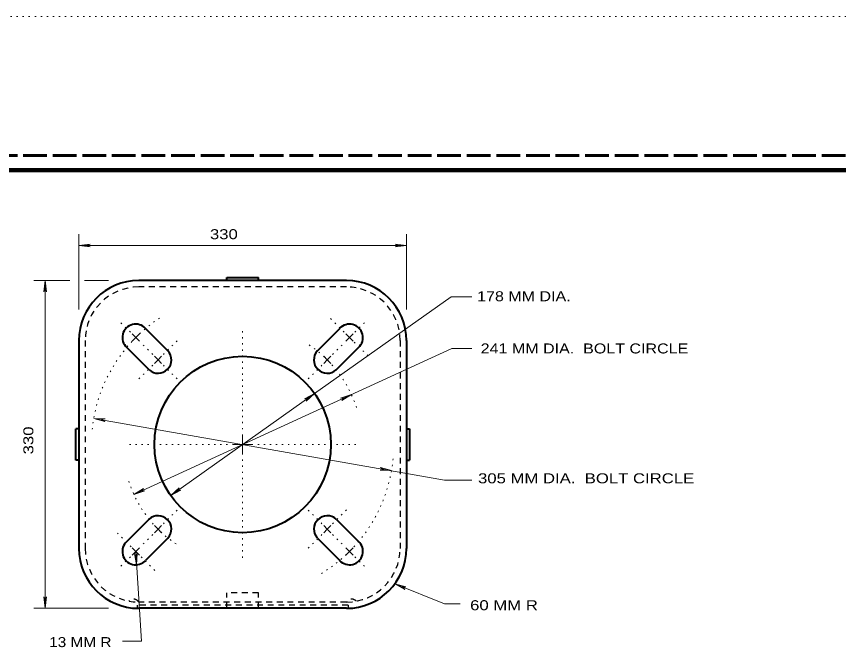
# Model space of a CAD drawing. Extents: x 312583 to 312854, y 144419 to 144597.
# Drawn here: x 312655.9 to 312718.5, y 144548.2 to 144596.8 of the extents above; entities that cross this region are included whole.
import ezdxf

# ---------------------------------------------------------------- set-up
doc = ezdxf.new("R2010")
doc.units = 0
doc.header["$LTSCALE"] = 0.3
for name, pattern in [('DOTTED', [1.5, 0.3, -1.2]), ('LONG_DASHED', [7.5, 6, -1.5]), ('SHORT_DASHED', [2.7, 1.5, -1.2])]:
    doc.linetypes.add(name, pattern=pattern)
for name, color, linetype, lineweight in [('1', 7, 'Continuous', 40), ('2', 7, 'Continuous', 13), ('63', 7, 'DOTTED', 13)]:
    doc.layers.add(name, color=color, linetype=linetype, lineweight=lineweight)

msp = doc.modelspace()

# ---------------------------------------------------------------- linework, layer by layer
at = {"layer": '1', "linetype": 'LONG_DASHED', "lineweight": 60}
msp.add_line((312851.75, 144586.2246), (312583.526, 144586.2246), dxfattribs=at)
at = {"layer": '1'}
for p, q in [((312681.0453, 144576.7003), (312665.2366, 144576.7003)), ((312671.945, 144576.938), (312674.337, 144576.938)), ((312667.46, 144571.3566), (312665.758, 144573.0586)), ((312678.822, 144571.3566), (312680.524, 144573.0586)), ((312660.6826, 144572.1463), (312660.6826, 144556.33)), ((312685.5993, 144572.1463), (312685.5993, 144556.33)), ((312666.0263, 144569.9153), (312664.3243, 144571.6173)), ((312680.2556, 144569.9153), (312681.9576, 144571.6173)), ((312660.445, 144563.0383), (312660.445, 144565.438)), ((312685.837, 144565.438), (312685.837, 144563.0383)), ((312666.0263, 144558.561), (312664.3243, 144556.859)), ((312680.2556, 144558.561), (312681.9576, 144556.859)), ((312667.46, 144557.1196), (312665.758, 144555.4176)), ((312678.822, 144557.1196), (312680.524, 144555.4176)), ((312681.0453, 144551.7836), (312665.2366, 144551.7836))]:
    msp.add_line(p, q, dxfattribs=at)
at = {"layer": '1', "linetype": 'SHORT_DASHED', "lineweight": 25}
for p, q in [((312681.0453, 144576.2173), (312665.2366, 144576.2173)), ((312661.158, 144572.1463), (312661.158, 144556.33)), ((312685.1163, 144572.1463), (312685.1163, 144556.33)), ((312674.337, 144552.972), (312671.945, 144552.972)), ((312681.0453, 144552.259), (312665.2366, 144552.259)), ((312665.114, 144552.0213), (312665.114, 144551.7836)), ((312681.168, 144552.0213), (312665.114, 144552.0213)), ((312681.168, 144552.0213), (312681.168, 144551.7836))]:
    msp.add_line(p, q, dxfattribs=at)
at = {"layer": '1', "lineweight": 158}
msp.add_lwpolyline([(312616.5, 144423.1446), (312616.5, 144585.0846), (312849, 144585.0846)], dxfattribs=at)
at = {"layer": '1'}
msp.add_circle((312673.139, 144564.2401), 6.7083, dxfattribs=at)
for centre, radius, start, end in [((312665.2328, 144572.1463), 4.5521, 90, 180), ((312681.0453, 144572.1463), 4.5521, 0, 90), ((312665.0066, 144572.3725), 1.0182, 42.40437, 227.592), ((312681.2715, 144572.3725), 1.0182, 312.40437, 137.592), ((312666.701, 144570.6781), 1.0182, 228.20522, 41.75743), ((312679.5771, 144570.6781), 1.0182, 138.20522, 311.75743), ((312666.701, 144557.802), 1.0182, 318.20522, 131.75743), ((312679.5771, 144557.802), 1.0182, 48.20522, 221.75743), ((312665.0066, 144556.1076), 1.0182, 132.40437, 317.592), ((312681.2715, 144556.1076), 1.0182, 222.40437, 47.592), ((312665.2328, 144556.3338), 4.5521, 180, 270), ((312681.0453, 144556.3338), 4.5521, 270, 0)]:
    msp.add_arc(centre, radius, start, end, dxfattribs=at)
at = {"layer": '1', "linetype": 'SHORT_DASHED', "lineweight": 25}
for centre, radius, start, end in [((312665.2328, 144572.1463), 4.0729, 90, 180), ((312681.0453, 144572.1463), 4.0729, 0, 90), ((312665.2328, 144556.3338), 4.0729, 180, 270), ((312681.0453, 144556.3338), 4.0729, 270, 0), ((312664.8359, 144552.0127), 0.4681, 32.01849, 137.4851), ((312681.4422, 144552.0127), 0.4681, 42.5149, 147.98151)]:
    msp.add_arc(centre, radius, start, end, dxfattribs=at)
at = {"layer": '1', "linetype": 'DOTTED', "lineweight": 13}
for start, end in [(17.97781, 57.71845), (197.8997, 238.39092)]:
    msp.add_arc((312673.139, 144564.2401), 9.1048, start, end, dxfattribs=at)
at = {"layer": '2'}
for p, q in [((312660.6826, 144574.4923), (312660.6826, 144580.2423)), ((312685.5993, 144574.4923), (312685.5993, 144580.2423)), ((312660.6826, 144579.3683), (312661.549, 144579.4756)), ((312685.5993, 144579.3683), (312660.6826, 144579.3683)), ((312660.6826, 144579.3683), (312661.549, 144579.261)), ((312661.549, 144579.4756), (312661.273, 144579.3683)), ((312661.549, 144579.261), (312661.273, 144579.3683)), ((312684.733, 144579.4756), (312685.009, 144579.3683)), ((312685.5993, 144579.3683), (312684.733, 144579.4756)), ((312684.733, 144579.261), (312685.009, 144579.3683)), ((312685.5993, 144579.3683), (312684.733, 144579.261)), ((312659.9926, 144576.7003), (312657.248, 144576.7003)), ((312658.122, 144576.7003), (312658.0146, 144575.834)), ((312658.122, 144551.7836), (312658.122, 144576.7003)), ((312658.122, 144576.7003), (312658.2293, 144575.834)), ((312662.9366, 144576.7003), (312661.1196, 144576.7003)), ((312658.0146, 144575.834), (312658.122, 144576.11)), ((312658.2293, 144575.834), (312658.122, 144576.11)), ((312665.0066, 144572.3686), (312664.7383, 144572.6446)), ((312665.0066, 144572.3686), (312664.7383, 144572.1003)), ((312665.0066, 144572.3686), (312665.2826, 144572.6446)), ((312665.0066, 144572.3686), (312665.2826, 144572.1003)), ((312681.2753, 144572.3686), (312680.9993, 144572.6446)), ((312681.2753, 144572.3686), (312680.9993, 144572.1003)), ((312681.2753, 144572.3686), (312681.5436, 144572.6446)), ((312681.2753, 144572.3686), (312681.5436, 144572.1003)), ((312664.861, 144560.447), (312689.0646, 144571.5406)), ((312689.0646, 144571.5406), (312690.5826, 144571.5406)), ((312666.701, 144570.6743), (312666.4326, 144570.9503)), ((312666.701, 144570.6743), (312666.977, 144570.9503)), ((312679.581, 144570.6743), (312679.305, 144570.9503)), ((312679.581, 144570.6743), (312679.8493, 144570.9503)), ((312666.701, 144570.6743), (312666.4326, 144570.406)), ((312666.701, 144570.6743), (312666.977, 144570.406)), ((312679.581, 144570.6743), (312679.305, 144570.406)), ((312679.581, 144570.6743), (312679.8493, 144570.406)), ((312667.667, 144560.3626), (312678.615, 144568.1136)), ((312678.615, 144568.1213), (312677.8483, 144567.7073)), ((312677.8483, 144567.7073), (312678.132, 144567.7763)), ((312678.615, 144568.1213), (312677.971, 144567.531)), ((312677.971, 144567.531), (312678.132, 144567.7763)), ((312681.4133, 144568.037), (312680.5853, 144567.7686)), ((312680.5853, 144567.7686), (312680.8766, 144567.7916)), ((312681.4133, 144568.037), (312680.6773, 144567.577)), ((312680.6773, 144567.577), (312680.8766, 144567.7916)), ((312661.8096, 144566.2276), (312688.505, 144561.5356)), ((312661.8096, 144566.2276), (312662.6453, 144565.9746)), ((312661.8096, 144566.2276), (312662.6836, 144566.1893)), ((312662.6836, 144566.1893), (312662.3923, 144566.128)), ((312662.6453, 144565.9746), (312662.3923, 144566.128)), ((312673.141, 144564.242), (312673.141, 144565.0086)), ((312673.141, 144564.242), (312672.3743, 144564.242)), ((312673.141, 144564.242), (312673.9076, 144564.242)), ((312673.141, 144564.242), (312673.141, 144563.4753)), ((312683.5983, 144562.2946), (312683.8896, 144562.3483)), ((312684.4646, 144562.2486), (312683.5983, 144562.2946)), ((312683.6366, 144562.5016), (312683.8896, 144562.3483)), ((312684.4646, 144562.2486), (312683.6366, 144562.5016)), ((312688.505, 144561.5356), (312690.5826, 144561.5356)), ((312664.861, 144560.447), (312665.6046, 144560.8993)), ((312665.6046, 144560.8993), (312665.3976, 144560.6923)), ((312667.667, 144560.3626), (312668.311, 144560.9453)), ((312668.311, 144560.9453), (312668.15, 144560.7)), ((312664.861, 144560.447), (312665.6966, 144560.7076)), ((312665.6966, 144560.7076), (312665.3976, 144560.6923)), ((312667.667, 144560.3626), (312668.4336, 144560.7766)), ((312668.4336, 144560.7766), (312668.15, 144560.7)), ((312666.701, 144557.802), (312666.4326, 144558.0703)), ((312666.701, 144557.802), (312666.4326, 144557.526)), ((312666.701, 144557.802), (312666.977, 144558.0703)), ((312666.701, 144557.802), (312666.977, 144557.526)), ((312679.581, 144557.802), (312679.305, 144558.0703)), ((312679.581, 144557.802), (312679.305, 144557.526)), ((312679.581, 144557.802), (312679.8493, 144558.0703)), ((312679.581, 144557.802), (312679.8493, 144557.526)), ((312665.0066, 144556.1076), (312664.7383, 144556.376)), ((312665.0066, 144556.1076), (312664.7383, 144555.8316)), ((312664.907, 144555.9466), (312665.0373, 144555.6783)), ((312665.0756, 144555.088), (312664.907, 144555.9466)), ((312665.0066, 144556.1076), (312665.2826, 144556.376)), ((312665.0066, 144556.1076), (312665.2826, 144555.8316)), ((312665.0066, 144556.1076), (312665.4436, 144549.292)), ((312665.1216, 144555.962), (312665.0373, 144555.6783)), ((312665.0756, 144555.088), (312665.1216, 144555.962)), ((312681.2753, 144556.1076), (312680.9993, 144556.376)), ((312681.2753, 144556.1076), (312680.9993, 144555.8316)), ((312681.2753, 144556.1076), (312681.5436, 144556.376)), ((312681.2753, 144556.1076), (312681.5436, 144555.8316)), ((312684.71, 144553.6313), (312685.4766, 144553.2096)), ((312684.71, 144553.6313), (312685.5533, 144553.409)), ((312685.4766, 144553.2096), (312685.2543, 144553.409)), ((312685.5533, 144553.409), (312685.2543, 144553.409)), ((312658.0146, 144552.65), (312658.122, 144552.374)), ((312658.122, 144551.7836), (312658.0146, 144552.65)), ((312658.2293, 144552.65), (312658.122, 144552.374)), ((312658.122, 144551.7836), (312658.2293, 144552.65)), ((312662.9366, 144551.7836), (312657.248, 144551.7836)), ((312665.4436, 144549.292), (312663.9946, 144549.292))]:
    msp.add_line(p, q, dxfattribs=at)
at = {"layer": '2', "lineweight": 40}
for p, q in [((312671.945, 144576.7003), (312671.945, 144576.938)), ((312674.337, 144576.7003), (312674.337, 144576.938)), ((312660.6826, 144565.438), (312660.445, 144565.438)), ((312685.5993, 144565.438), (312685.837, 144565.438)), ((312660.6826, 144563.0383), (312660.445, 144563.0383)), ((312685.5993, 144563.0383), (312685.837, 144563.0383))]:
    msp.add_line(p, q, dxfattribs=at)
at = {"layer": '2', "linetype": 'DOTTED'}
for p, q in [((312664.6003, 144572.775), (312663.78, 144573.5953)), ((312680.869, 144572.775), (312679.7573, 144573.8866)), ((312681.6816, 144572.775), (312682.4943, 144573.5953)), ((312673.141, 144565.392), (312673.141, 144573.0586)), ((312667.1073, 144571.0806), (312668.242, 144572.2153)), ((312666.2946, 144571.0806), (312665.39, 144571.9853)), ((312679.9873, 144571.0806), (312680.892, 144571.9853)), ((312681.628, 144572.016), (312682.8163, 144570.8353)), ((312666.2946, 144570.268), (312665.183, 144569.164)), ((312667.1073, 144570.268), (312668.15, 144569.233)), ((312679.1746, 144570.268), (312678.132, 144569.233)), ((312671.991, 144564.242), (312664.3243, 144564.242)), ((312674.291, 144564.242), (312681.9576, 144564.242)), ((312673.141, 144563.092), (312673.141, 144555.4253)), ((312667.1073, 144558.2083), (312668.15, 144559.2433)), ((312679.1746, 144558.2083), (312678.132, 144559.2433)), ((312679.9873, 144558.2083), (312681.0913, 144559.32)), ((312664.654, 144556.4603), (312663.4656, 144557.6486)), ((312666.2946, 144557.3956), (312665.39, 144556.491)), ((312679.1746, 144557.3956), (312678.04, 144556.261)), ((312679.9873, 144557.3956), (312680.892, 144556.491)), ((312664.6003, 144555.7013), (312663.78, 144554.881)), ((312665.413, 144555.7013), (312666.5246, 144554.5896)), ((312681.6816, 144555.7013), (312682.4943, 144554.881))]:
    msp.add_line(p, q, dxfattribs=at)
at = {"layer": '2', "linetype": 'SHORT_DASHED', "lineweight": 25}
for p, q in [((312671.945, 144551.7836), (312671.945, 144552.972)), ((312674.337, 144551.7836), (312674.337, 144552.972))]:
    msp.add_line(p, q, dxfattribs=at)
at = {"layer": '2'}
for points in [[(312678.615, 144568.1136), (312689.0103, 144575.4733), (312690.5826, 144575.4733)], [(312684.71, 144553.6313), (312688.4973, 144552.1133), (312689.6933, 144552.1133)]]:
    msp.add_lwpolyline(points, dxfattribs=at)
at = {"layer": '2', "linetype": 'DOTTED'}
for start, end in [(123.32792, 175.65109), (301.37479, 355.15985)]:
    msp.add_arc((312673.139, 144564.2401), 11.501, start, end, dxfattribs=at)
at = {"layer": '63'}
msp.add_line((312601.2, 144596.7846), (312853.5, 144596.7846), dxfattribs=at)

# ---------------------------------------------------------------- texts
at = {"layer": '2'}
for s, width, p in [('330 ', 1.25, (312670.6513, 144579.8484)), ('178 MM DIA.', 1.2, (312690.9783, 144575.129)), ('241 MM DIA.  BOLT CIRCLE', 1.2, (312691.2496, 144571.1601)), ('305 MM DIA.  BOLT CIRCLE', 1.25, (312691.0466, 144561.2875)), ('60 MM R', 1.25, (312690.4465, 144551.637)), ('13 MM R', 1.15, (312658.4215, 144548.8329))]:
    msp.add_text(s, height=0.76, dxfattribs=dict(at, width=width)).set_placement(p)
at = {"layer": '2', "width": 1.25}
msp.add_text('330 ', height=0.76, rotation=90, dxfattribs=at).set_placement((312657.2173, 144563.4872))

doc.saveas('drawing.dxf')
